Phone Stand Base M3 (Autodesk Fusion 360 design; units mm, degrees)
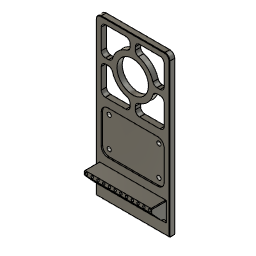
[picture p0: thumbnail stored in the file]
sketch "Sketch1" plane through (0, 0, 0) normal (0, 0, 1) x axis (1, 0, 0)
  line L1 (190.5, 0) -> (0, 0)
  line L2 (190.5, 88.9) -> (190.5, 0)
  line L3 (0, 88.9) -> (190.5, 88.9)
  line L4 (0, 0) -> (0, 88.9)
  point P1 (0, 0)
  point P2 (0, 0)
  point P3 (190.5, 0)
  point P5 (0, 88.9)
  horizontal L1
  vertical L2
  horizontal L3
  vertical L4
  coincident P1 P2
  dimension "d1" distance P2 P3 = 190.5
  dimension "d2" distance P2 P5 = 88.9
extrude "Extrude1" new body sketch "Sketch1" along normal blind 6.35
sketch "Sketch2" plane through (0, 0, 6.35) normal (0, 0, 1) x axis (-1, 0, 0)
  line L1 (0, 0) -> (0, -88.9)
  line L2 (-190.5, 0) -> (0, 0)
  line L3 (-190.5, -88.9) -> (-190.5, 0)
  line L4 (0, -88.9) -> (-190.5, -88.9)
  line L5 (-36.83, -85.09) -> (-19.05, -85.09)
  line L6 (-36.83, -3.81) -> (-36.83, -85.09)
  line L7 (-19.05, -3.81) -> (-36.83, -3.81)
  line L8 (-19.05, -85.09) -> (-19.05, -3.81)
  horizontal L5
  vertical L6
  horizontal L7
  vertical L8
  dimension "d5" distance L1 L8 = 19.05
  dimension "d6" distance L6 L8 = 17.78
  dimension "d7" distance L4 L5 = 3.81
  dimension "d8" distance L2 L7 = 3.81
extrude "Extrude2" add sketch "Sketch2" profile of L5 L6 L7 L8 along normal blind 17.78
fillet "Fillet1" radius 6
chamfer "Chamfer1" distance 12.7 distance 11.43
fillet "Fillet2" radius 6
chamfer "Chamfer2" distance 0.5 distance 0.508
fillet "Fillet4" radius 0.75
sketch "Sketch5" plane through (0, 0, 6.35) normal (0, 0, 1) x axis (-1, 0, 0)
  line L1 (-36.08, -85.09) -> (-13.05, -85.09)
  line L2 (-36.83, -4.56) -> (-36.83, -84.34)
  line L3 (-13.05, -3.81) -> (-36.08, -3.81)
  line L4 (-13.05, -85.09) -> (-13.05, -3.81)
  line L5 (-184.5, -0.5) -> (-0.5, -0.5)
  line L6 (-190, -82.9) -> (-190, -6)
  line L7 (-0.5, -88.4) -> (-184.5, -88.4)
  line L8 (-0.5, -0.5) -> (-0.5, -88.4)
  line L9 (0, -88.9) -> (-184.5, -88.9)
  line L10 (-190.5, -82.9) -> (-190.5, -6)
  line L11 (-184.15, -77.47) -> (-184.15, -52.705)
  line L12 (-154.305, -82.55) -> (-179.07, -82.55)
  line L13 (-184.15, -44.45) -> (-171.45, -44.45)
  line L14 (-190.5, -44.45) -> (-190, -44.45)
  line L15 (-179.07, -47.625) -> (-171.2508, -47.625)
  line L16 (-146.05, -82.55) -> (-146.05, -69.85)
  line L17 (-146.05, -88.9) -> (-146.05, -88.4)
  line L18 (-149.225, -77.47) -> (-149.225, -69.6508)
  line L19 (-149.225, -88.9) -> (-149.225, -88.4)
  arc A1 centre (-36.08, -84.34) radius 0.75 clockwise from (-36.08, -85.09) to (-36.83, -84.34)
  arc A2 centre (-36.08, -4.56) radius 0.75 clockwise from (-36.83, -4.56) to (-36.08, -3.81)
  arc A3 centre (-184.5, -6) radius 5.5 clockwise from (-190, -6) to (-184.5, -0.5)
  arc A4 centre (-184.5, -82.9) radius 5.5 clockwise from (-184.5, -88.4) to (-190, -82.9)
  circle C1 centre (-146.05, -44.45) radius 19.05
  circle C2 centre (-146.05, -44.45) radius 25.4
  arc A5 centre (-179.07, -77.47) radius 5.08 clockwise from (-179.07, -82.55) to (-184.15, -77.47)
  arc A6 centre (-154.305, -77.47) radius 5.08 clockwise from (-149.225, -77.47) to (-154.305, -82.55)
  arc A7 centre (-179.07, -52.705) radius 5.08 clockwise from (-184.15, -52.705) to (-179.07, -47.625)
  point P24 (-149.225, -69.6508)
  point P25 (-146.05, -69.85)
  point P26 (-171.2508, -47.625)
  point P27 (-171.45, -44.45)
  point P28 (-190.5, -44.45)
  point P29 (-184.15, -44.45)
  point P30 (-190, -44.45)
  point P31 (-146.05, -82.55)
  point P32 (-146.05, -88.4)
  point P33 (-149.225, -88.4)
  point P34 (-149.225, -88.9)
  point P35 (-146.05, -88.9)
  point P18 (-146.05, -44.45)
  coincident C2 P24
  coincident C2 P25
  coincident C2 P26
  coincident C2 P27
  coincident L10 P28
  coincident L11 P29
  coincident L6 P30
  collinear L13 L14
  coincident L12 P31
  coincident L7 P32
  collinear L16 L17
  coincident L7 P33
  collinear L18 L19
  coincident L9 P34
  coincident L9 P35
  tangent L12 A5
  tangent L11 A5
  tangent L18 A6
  tangent L12 A6
  tangent L11 A7
  tangent L15 A7
  dimension "d51" distance P18 L9 = 44.45
  dimension "d52" distance P18 L10 = 44.45
  dimension "d53" diameter C1 = 38.1
  dimension "d54" = 6.35
  dimension "d58" radius A5 = 5.08
  dimension "d59" radius A6 = 5.08
  dimension "d60" radius A7 = 5.08
extrude "Extrude5" cut sketch "Sketch5" profile of C1 C2 L19 L15 L11 L12 A5 A6 A7 no distance stored
fillet "Fillet5" radius 5
fillet "Fillet6" radius 5
circular_pattern "C-Pattern1" TotalAngle 360
fillet "Fillet7" radius 5
sketch "Sketch6" plane through (0, 0, 6.35) normal (0, 0, 1) x axis (-1, 0, 0)
  line L1 (-107.95, -77.47) -> (-107.95, -52.705)
  line L2 (-137.795, -82.55) -> (-113.03, -82.55)
  line L3 (-142.875, -73.7302) -> (-142.875, -77.47)
  line L4 (-113.03, -47.625) -> (-116.7698, -47.625)
  line L5 (-113.03, -6.35) -> (-137.795, -6.35)
  line L6 (-107.95, -36.195) -> (-107.95, -11.43)
  line L7 (-116.7698, -41.275) -> (-113.03, -41.275)
  line L8 (-142.875, -11.43) -> (-142.875, -15.1698)
  line L9 (-184.15, -11.43) -> (-184.15, -36.195)
  line L10 (-154.305, -6.35) -> (-179.07, -6.35)
  line L11 (-149.225, -15.1698) -> (-149.225, -11.43)
  line L12 (-179.07, -41.275) -> (-175.3302, -41.275)
  line L13 (-179.07, -82.55) -> (-154.305, -82.55)
  line L14 (-184.15, -52.705) -> (-184.15, -77.47)
  line L15 (-175.3302, -47.625) -> (-179.07, -47.625)
  line L16 (-149.225, -77.47) -> (-149.225, -73.7302)
  line L17 (-36.08, -85.09) -> (-13.05, -85.09)
  line L18 (-36.83, -4.56) -> (-36.83, -84.34)
  line L19 (-13.05, -3.81) -> (-36.08, -3.81)
  line L20 (-13.05, -85.09) -> (-13.05, -3.81)
  line L21 (-184.5, -0.5) -> (-0.5, -0.5)
  line L22 (-190, -82.9) -> (-190, -6)
  line L23 (-0.5, -88.4) -> (-184.5, -88.4)
  line L24 (-0.5, -0.5) -> (-0.5, -88.4)
  line L25 (-46.355, -82.55) -> (-98.425, -82.55)
  line L26 (-46.355, -6.35) -> (-46.355, -82.55)
  line L27 (-98.425, -6.35) -> (-46.355, -6.35)
  line L28 (-98.425, -82.55) -> (-98.425, -6.35)
  line L29 (0, -88.9) -> (-184.5, -88.9)
  arc A1 centre (-113.03, -52.705) radius 5.08 clockwise from (-113.03, -47.625) to (-107.95, -52.705)
  arc A2 centre (-113.03, -77.47) radius 5.08 clockwise from (-107.95, -77.47) to (-113.03, -82.55)
  arc A3 centre (-137.795, -77.47) radius 5.08 clockwise from (-137.795, -82.55) to (-142.875, -77.47)
  arc A4 centre (-137.875, -73.7302) radius 5 clockwise from (-142.875, -73.7302) to (-139.2196, -68.9144)
  arc A5 centre (-146.05, -44.45) radius 25.4 clockwise from (-121.5856, -51.2804) to (-139.2196, -68.9144)
  arc A6 centre (-116.7698, -52.625) radius 5 clockwise from (-121.5856, -51.2804) to (-116.7698, -47.625)
  arc A7 centre (-137.795, -11.43) radius 5.08 clockwise from (-142.875, -11.43) to (-137.795, -6.35)
  arc A8 centre (-113.03, -11.43) radius 5.08 clockwise from (-113.03, -6.35) to (-107.95, -11.43)
  arc A9 centre (-113.03, -36.195) radius 5.08 clockwise from (-107.95, -36.195) to (-113.03, -41.275)
  arc A10 centre (-116.7698, -36.275) radius 5 clockwise from (-116.7698, -41.275) to (-121.5856, -37.6196)
  arc A11 centre (-146.05, -44.45) radius 25.4 clockwise from (-139.2196, -19.9856) to (-121.5856, -37.6196)
  arc A12 centre (-137.875, -15.1698) radius 5 clockwise from (-139.2196, -19.9856) to (-142.875, -15.1698)
  arc A13 centre (-179.07, -36.195) radius 5.08 clockwise from (-179.07, -41.275) to (-184.15, -36.195)
  arc A14 centre (-179.07, -11.43) radius 5.08 clockwise from (-184.15, -11.43) to (-179.07, -6.35)
  arc A15 centre (-154.305, -11.43) radius 5.08 clockwise from (-154.305, -6.35) to (-149.225, -11.43)
  arc A16 centre (-154.225, -15.1698) radius 5 clockwise from (-149.225, -15.1698) to (-152.8804, -19.9856)
  arc A17 centre (-146.05, -44.45) radius 25.4 clockwise from (-170.5144, -37.6196) to (-152.8804, -19.9856)
  arc A18 centre (-175.3302, -36.275) radius 5 clockwise from (-170.5144, -37.6196) to (-175.3302, -41.275)
  arc A19 centre (-154.305, -77.47) radius 5.08 clockwise from (-149.225, -77.47) to (-154.305, -82.55)
  arc A20 centre (-179.07, -77.47) radius 5.08 clockwise from (-179.07, -82.55) to (-184.15, -77.47)
  arc A21 centre (-179.07, -52.705) radius 5.08 clockwise from (-184.15, -52.705) to (-179.07, -47.625)
  arc A22 centre (-175.3302, -52.625) radius 5 clockwise from (-175.3302, -47.625) to (-170.5144, -51.2804)
  arc A23 centre (-146.05, -44.45) radius 25.4 clockwise from (-152.8804, -68.9144) to (-170.5144, -51.2804)
  arc A24 centre (-154.225, -73.7302) radius 5 clockwise from (-152.8804, -68.9144) to (-149.225, -73.7302)
  circle C1 centre (-146.05, -44.45) radius 19.05
  arc A25 centre (-36.08, -84.34) radius 0.75 clockwise from (-36.08, -85.09) to (-36.83, -84.34)
  arc A26 centre (-36.08, -4.56) radius 0.75 clockwise from (-36.83, -4.56) to (-36.08, -3.81)
  arc A27 centre (-184.5, -6) radius 5.5 clockwise from (-190, -6) to (-184.5, -0.5)
  arc A28 centre (-184.5, -82.9) radius 5.5 clockwise from (-184.5, -88.4) to (-190, -82.9)
  horizontal L25
  vertical L26
  horizontal L27
  vertical L28
  dimension "d70" distance L25 L29 = 6.35
  dimension "d71" distance L25 L27 = 76.2
  dimension "d72" distance L6 L28 = 9.525
  dimension "d73" distance L18 L26 = 9.525
extrude "Extrude6" cut sketch "Sketch6" profile of L25 L26 L27 L28 against normal blind 1.6
fillet "Fillet8" radius 8
hole "Hole2" HoleDiameter 5.035 TipAngle 118
hole "Hole3" HoleDiameter 5.035 TipAngle 118
hole "Hole4" HoleDiameter 5.035 TipAngle 118
hole "Hole5" HoleDepth 30.48 HoleDiameter 5.035 TipAngle 118
hole "Hole6" HoleDepth 24.13 HoleDiameter 3 TipAngle 118 RefDim1 2.54 RefDim2 6.35
rectangular_pattern "R-Pattern2" countU 12 uSpaceDistance 76.2 vSpaceDistance 0
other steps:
thread "Thread2"
thread "Thread3"
thread "Thread4"
thread "Thread5"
